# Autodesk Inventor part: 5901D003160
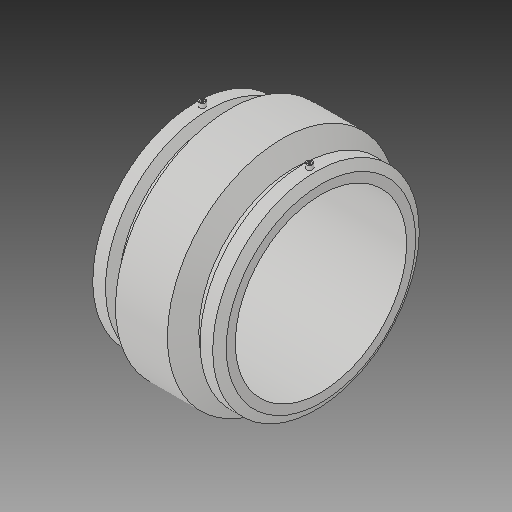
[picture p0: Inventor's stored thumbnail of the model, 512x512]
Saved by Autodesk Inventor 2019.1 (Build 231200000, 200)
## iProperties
Created: 2017-06
Part Number: 5901D003160
Material: Generic
Description: PLASSON COUPLER 16''DIPS
Document SubType Name: Modeling
Designer: KIM
Mass: 96874 g
Surface Area: 34549.7 cm^2
Volume: 96874 cm^3
Density: 1 g/cm^3
Appearance: Default
Author: KIM
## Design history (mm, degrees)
derived "5901D.ipt"
feature "Solid1::5901D.ipt"
tag "TaggingFeature1"
body "Solid1"
other parameters: "d13" = 306.832, "d15" = 152.908, "d16" = 152.908, "d17" = 404.6, "d22" = 508, "d23" = 541.02, "d24" = 447.04, "d25" = 150 deg, "d26" = 122.7328, "d27" = 120 deg, "d29" = 254, "d35" = 15, "d39" = 0, "d40" = 4, "d41" = 14, "d42" = 0, "d44" = 53.5178, "d45" = 404.6, "d47" = 0, "d48" = 243.84, "d49" = 53.5178, "d50" = 60 deg, "d57" = 65.786, "d58" = 53.5178, "d62" = 404.6, "d65" = 282.448, "d67" = 5.27613, "d68" = 21.15863, "d69" = 21.80789, "d70" = 21.71015, "d71" = 20.5722, "d72" = 20.71531, "d73" = 561.2638, "d76" = 122.7328, "d77" = 447.04, "d_" = 404.6, "L_" = 306.832, "L_1" = 152.908, "D_" = 541.02, "A_" = 254, "A_1" = 25.4, "d60" = 187.96
